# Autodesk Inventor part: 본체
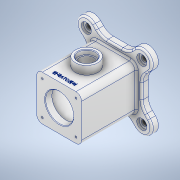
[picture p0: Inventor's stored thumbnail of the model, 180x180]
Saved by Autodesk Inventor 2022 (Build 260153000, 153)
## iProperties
Created: 2022-05
Part Number: 본체
Material: 알루미늄 6061
Document SubType Name: Modeling
Designer: Admin
Mass: 1072.03 g
Surface Area: 878.934 cm^2
Volume: 397.049 cm^3
Density: 2.7 g/cm^3
Appearance: 알루미늄 - 평지
Author: Admin
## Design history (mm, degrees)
sketch "스케치1"
  geometry: L1 (-40, 40)-(40, 40); L2 (40, 40)-(40, -40); L3 (40, -40)-(-40, -40); L4 (-40, -40)-(-40, 40); L5 (-40, 40)-(40, -40); L6 (40, 40)-(-40, -40); 3 further points
  constraints: 12 end point, 3 midpoint, 2 parallel, 1 coincident, 1 horizontal, 1 perpendicular
  dimensions: "d0" = 80 distance of L1.start L1.end; "d1" = 80 distance of L1.end L2.end
extrude "돌출1" new body sketch "스케치1" distance "d2" = 110; taper "d3" = 0 deg
sketch "스케치2"
  geometry: L1 (-49, 49)-(49, 49); L2 (49, 49)-(49, -49); L3 (49, -49)-(-49, -49); L4 (-49, -49)-(-49, 49); L5 (-49, 49)-(49, -49); L6 (49, 49)-(-49, -49); L7 (-61.728, 36.272)-(-49, 23.544); L8 (93.8, 0)-(-93.8, 0) reference; L9 (0, -93.8)-(0, 93.8) reference; L10 (-36.272, 61.728)-(-23.544, 49); L11 (36.272, 61.728)-(23.544, 49); L12 (61.728, 36.272)-(49, 23.544); L13 (-36.272, -61.728)-(-23.544, -49); L14 (-61.728, -36.272)-(-49, -23.544); L15 (36.272, -61.728)-(23.544, -49); L16 (61.728, -36.272)-(49, -23.544); A1 r 18 centre (-49, 49) between (-61.728, 36.272) and (-36.272, 61.728); A2 r 18 centre (49, 49) between (61.728, 36.272) and (36.272, 61.728); A3 r 18 centre (-49, -49) between (-61.728, -36.272) and (-36.272, -61.728); A4 r 18 centre (49, -49) between (61.728, -36.272) and (36.272, -61.728); 9 further points
  constraints: 28 end point, 15 symmetric about line, 8 point on circle, 4 centre point, 4 parallel, 3 midpoint, 2 coincident, 2 point on line, 2 tangent, 1 horizontal, 1 perpendicular, 3 other
  dimensions: "d4" = 98 distance of L1.end L2.end; "d5" = 98 distance of L2.end L3.end; "d6" = 36 diameter of A1
extrude "돌출2" join sketch "스케치2" distance "d7" = 12; taper "d8" = 0 deg
fillet "모깎기1" dims "d9" = 25
sketch "스케치3"
  geometry: L1 (-27, 98)-(3.728, 98) reference; L2 (26.811, 110)-(53.189, 110) reference; C1 r 20 at (40, 49); 3 further points
  constraints: 1 centre point, 1 midpoint, 1 vertical alignment
  dimensions: "d10" = 40 diameter of C1; "d11" = 49 distance from line of L1 C1.centre
extrude "돌출3" join sketch "스케치3" distance "d12" = 15; taper "d13" = 0 deg
node "작업 평면1"
sketch "스케치6"
  geometry: L1 (0, 0)-(0, 110); L2 (40, 110)-(-40, 110) reference; L3 (0, 110)-(25, 110); L4 (25, 98)-(25, 110); L5 (25, 98)-(35, 98); L6 (35, 98)-(35, 12); L7 (35, 12)-(25, 12); L8 (25, 12)-(25, 0); L9 (25, 0)-(0, 0)
  constraints: 16 end point, 5 perpendicular, 1 horizontal, 1 midpoint, 1 point on line
  dimensions: "d15" = 12 distance of L4.start L3.end; "d16" = 12 distance of L7.end L8.end; "d17" = 50 diameter of L4 L1; "d18" = 50 diameter of L8 L1; "d19" = 70 diameter of L6 L1
revolve "회전1" sketch "스케치6" stored, may be unused: angle "d20" = 90 deg
sketch "스케치7"
  geometry: C1 r 20 at (0, 0) reference; C2 r 15 at (0, 0); 1 further point
  constraints: 1 centre point, 1 coincident
  dimensions: "d21" = 30 diameter of C2
extrude "돌출4" cut sketch "스케치7" distance "d22" = 8; taper "d23" = 0 deg
sketch "스케치8"
  geometry: C1 r 15 at (0, 0) reference; C2 r 12.5 at (0, 0); 1 further point
  constraints: 1 centre point, 1 coincident
  dimensions: "d24" = 25 diameter of C2
extrude "돌출5" cut sketch "스케치8" stored distance "d25" = 8; taper "d26" = 0 deg
sketch "스케치9"
  geometry: L1 (-30, 30)-(30, 30); L2 (30, 30)-(30, -30); L3 (30, -30)-(-30, -30); L4 (-30, -30)-(-30, 30); L5 (-30, 30)-(30, -30); L6 (30, 30)-(-30, -30); 7 further points
  constraints: 12 end point, 5 coincident, 3 midpoint, 2 parallel, 1 horizontal, 1 perpendicular
  dimensions: "d27" = 60 distance of L1.end L2.end; "d28" = 60 distance of L1.start L1.end
hole "구멍1" sketch "스케치9" at (-30, 30), (30, 30), (-30, -30), (30, -30) diameter "d29" = 3.242; stored, may be unused: countersink angle "d33" = 90 deg, drill point angle "d35" = 90 deg; dims "d30" = 8, "d31" = 4, "d32" = 2, "d34" = 10
node "작업 평면2"
sketch "스케치12" dims "d38" = 140
  geometry: L1 (0, -98.604)-(0, 101.624) reference; L2 (98, 0)-(-98, 0) reference; L3 (-49.497, 49.497)-(0, 0); C1 r 25 at (0, 0) reference; C2 r 5 at (-49.497, 49.497); C3 r 5 at (49.497, 49.497); C4 r 5 at (-49.497, -49.497); C5 r 5 at (49.497, -49.497); 1 further point
  constraints: 4 centre point, 3 symmetric about line, 2 end point, 1 coincident, 6 other
  dimensions: "d41" = 10 diameter of C2; "d42" = 45 deg angle of L1 L3
extrude "돌출6" cut sketch "스케치12" extent not by distance; stored distance "d43" = 0; taper "d44" = 0 deg
sketch "스케치13"
  geometry: C1 r 5 at (-49.497, 49.497) reference; C2 r 9 at (-49.497, 49.497); C3 r 5 at (49.497, 49.497) reference; C4 r 9 at (49.497, 49.497); C5 r 5 at (-49.497, -49.497) reference; C6 r 9 at (-49.497, -49.497); C7 r 5 at (49.497, -49.497) reference; C8 r 9 at (49.497, -49.497); 1 further point
  constraints: 4 centre point, 4 coincident
  dimensions: "d45" = 18 diameter of C2; "d46" = 18 diameter of C4; "d47" = 18 diameter of C6; "d48" = 18 diameter of C8
extrude "돌출7" cut sketch "스케치13" distance "d49" = 4; taper "d50" = 0 deg
fillet "모깎기2" dims "d51" = 10
fillet "모깎기3" dims "d52" = 3
chamfer "모따기1" distance "d53" = 1; stored, may be unused: second distance "d54" = 2, angle "d55" = 45 deg
sketch "스케치14"
  geometry: L1 (60, 0)-(0, 0) reference; L2 (-10, 95)-(-10, 0) reference; 2 further points
  constraints: 1 other
  dimensions: "d56" = 10 distance from line of L1 point (30, 10); "d57" = 40 distance from line of L2 point (30, 10)
feature "엠보싱1" sketch "스케치14" dims "d4" = 98, "d5" = 98, "d6" = 36, "d58" = 0.5, "d59" = 0
node "솔리드1"
mirror "미러1"
feature "A9D066F2-1C7D-4E18-AEED-F7BC21143FA4" dims "d29" = 3.242, "d30" = 8, "d31" = 4, "d32" = 2, "d33" = 90 deg, "d34" = 10, "d35" = 90 deg
other parameters: "d14" = 0, "d36" = -55
